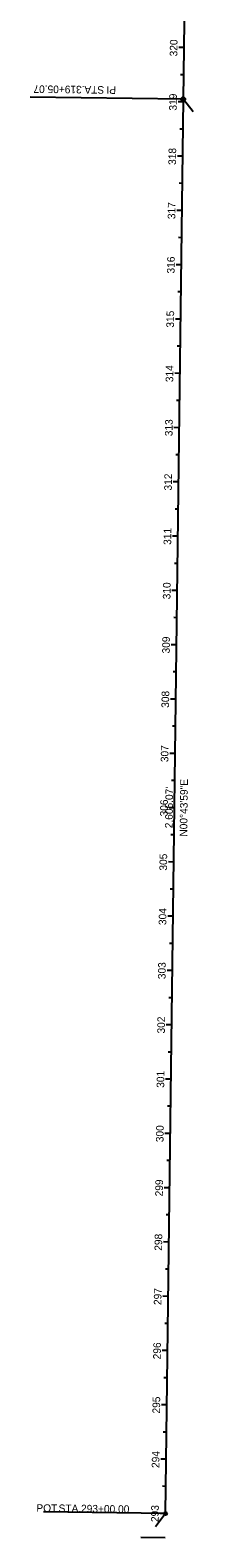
# Model space of a CAD drawing. Extents: x 1652268 to 1652613, y 604222 to 609731.
# Drawn here: x 1652268 to 1652586, y 604222 to 606999 of the extents above; entities that cross this region are included whole.
import ezdxf

# ---------------------------------------------------------------- set-up
doc = ezdxf.new("R2010")
doc.units = 0
for name, color, linetype in [('DT_X_Contour_Major', 7, 'Continuous'), ('DT_X_Contour_Minor', 7, 'Continuous'), ('DT_X_Contour_Text', 7, 'Continuous'), ('DT_X_Terrain_Ground_Line', 7, 'Continuous'), ('DT_X_Triangles', 7, 'Continuous'), ('PV_X_Curb', 7, 'Continuous')]:
    doc.layers.add(name, color=color, linetype=linetype)

msp = doc.modelspace()

# ---------------------------------------------------------------- linework, layer by layer
at = {"layer": 'DT_X_Contour_Minor'}
for p, q in [((1652550.1, 606872.1), (1652268, 606875.6)), ((1652517.5, 604267.2), (1652292.6, 604270.1))]:
    msp.add_line(p, q, dxfattribs=at)
for centre, radius in [((1652550.1, 606872.1), 3.76), ((1652517.5, 604267.2), 3)]:
    msp.add_circle(centre, radius, dxfattribs=at)
at = {"layer": 'DT_X_Contour_Text'}
for p, q in [((1652552, 606967), (1652542, 606967.1)), ((1652551.4, 606917), (1652545.4, 606917.1)), ((1652550.8, 606867), (1652540.8, 606867.1)), ((1652550.2, 606817), (1652544.2, 606817.1)), ((1652549.5, 606767), (1652539.5, 606767.1)), ((1652548.9, 606717), (1652542.9, 606717.1)), ((1652548.2, 606667), (1652538.2, 606667.1)), ((1652547.6, 606617), (1652541.6, 606617.1)), ((1652547, 606567), (1652537, 606567.2)), ((1652546.3, 606517), (1652540.3, 606517.1)), ((1652545.7, 606467), (1652535.7, 606467.2)), ((1652545, 606417), (1652539, 606417.1)), ((1652544.4, 606367), (1652534.4, 606367.2)), ((1652543.8, 606317), (1652537.8, 606317.1)), ((1652543.1, 606267), (1652533.1, 606267.2)), ((1652542.5, 606217.1), (1652536.5, 606217.1)), ((1652541.8, 606167.1), (1652531.8, 606167.2)), ((1652541.2, 606117.1), (1652535.2, 606117.1)), ((1652540.6, 606067.1), (1652530.6, 606067.2)), ((1652539.9, 606017.1), (1652533.9, 606017.1)), ((1652539.3, 605967.1), (1652529.3, 605967.2)), ((1652538.6, 605917.1), (1652532.6, 605917.2)), ((1652538, 605867.1), (1652528, 605867.2)), ((1652537.4, 605817.1), (1652531.4, 605817.2)), ((1652536.7, 605767.1), (1652526.7, 605767.2)), ((1652536.1, 605717.1), (1652530.1, 605717.2)), ((1652535.4, 605667.1), (1652525.4, 605667.2)), ((1652534.8, 605617.1), (1652528.8, 605617.2)), ((1652534.2, 605567.1), (1652524.2, 605567.2)), ((1652533.5, 605517.1), (1652527.5, 605517.2)), ((1652532.9, 605467.1), (1652522.9, 605467.2)), ((1652532.2, 605417.1), (1652526.2, 605417.2)), ((1652531.6, 605367.1), (1652521.6, 605367.2)), ((1652531, 605317.1), (1652525, 605317.2)), ((1652530.3, 605267.1), (1652520.3, 605267.3)), ((1652529.7, 605217.1), (1652523.7, 605217.2)), ((1652529, 605167.1), (1652519, 605167.3)), ((1652528.4, 605117.1), (1652522.4, 605117.2)), ((1652527.8, 605067.1), (1652517.8, 605067.3)), ((1652527.1, 605017.2), (1652521.1, 605017.2)), ((1652526.5, 604967.2), (1652516.5, 604967.3)), ((1652525.8, 604917.2), (1652519.8, 604917.2)), ((1652525.2, 604867.2), (1652515.2, 604867.3)), ((1652524.6, 604817.2), (1652518.6, 604817.2)), ((1652523.9, 604767.2), (1652513.9, 604767.3)), ((1652523.3, 604717.2), (1652517.3, 604717.3)), ((1652522.6, 604667.2), (1652512.7, 604667.3)), ((1652522, 604617.2), (1652516, 604617.3)), ((1652521.4, 604567.2), (1652511.4, 604567.3)), ((1652520.7, 604517.2), (1652514.7, 604517.3)), ((1652520.1, 604467.2), (1652510.1, 604467.3)), ((1652519.5, 604417.2), (1652513.5, 604417.3)), ((1652518.8, 604367.2), (1652508.8, 604367.3)), ((1652518.2, 604317.2), (1652512.2, 604317.3)), ((1652517.5, 604267.2), (1652507.5, 604267.3))]:
    msp.add_line(p, q, dxfattribs=at)
at = {"layer": 'DT_X_Terrain_Ground_Line'}
for p, q in [((1652550.9, 606872.1), (1652586.4, 609713.4)), ((1652517.5, 604267.2), (1652550.9, 606872.1))]:
    msp.add_line(p, q, dxfattribs=at)
at = {"layer": 'PV_X_Curb'}
for p, q in [((1652550.9, 606872.1), (1652568.6, 606849.5)), ((1652517.5, 604267.2), (1652499.1, 604242.9)), ((1652517, 604222.4), (1652472, 604223))]:
    msp.add_line(p, q, dxfattribs=at)

# ---------------------------------------------------------------- texts
at = {"layer": 'DT_X_Contour_Major'}
msp.add_text("2,605.07'", height=14, rotation=89.267, dxfattribs=at).set_placement((1652530.6, 605529.2))
at = {"layer": 'DT_X_Contour_Minor'}
for s, rotation, p in [('319+05.07', 179.2843, (1652363.2, 606896.6)), (' STA. ', 179.2843, (1652409.8, 606896)), ('PI', 179.2843, (1652426.4, 606895.8)), ('POT', 359.267, (1652279.5, 604270.4)), (' STA. ', 359.267, (1652315.2, 604270)), ('293+00.00', 359.267, (1652361.8, 604269.4))]:
    msp.add_text(s, height=14, rotation=rotation, dxfattribs=at).set_placement(p)
at = {"layer": 'DT_X_Contour_Text'}
for s, rotation, p in [('320', 89.2843, (1652539.3, 606950.8)), ('319', 89.267, (1652538.1, 606851)), ('318', 89.267, (1652536.8, 606750.9)), ('317', 89.267, (1652535.5, 606651)), ('316', 89.267, (1652534.2, 606550.9)), ('315', 89.267, (1652533, 606451.2)), ('314', 89.267, (1652531.7, 606350.8)), ('313', 89.267, (1652530.4, 606251.2)), ('312', 89.267, (1652529.1, 606151.2)), ('311', 89.267, (1652527.9, 606051.1)), ('310', 89.267, (1652526.6, 605950.9)), ('309', 89.267, (1652525.3, 605851.1)), ('308', 89.267, (1652524, 605751)), ('307', 89.267, (1652522.7, 605651)), ('306', 89.267, (1652521.5, 605551)), ('305', 89.267, (1652520.2, 605451.2)), ('304', 89.267, (1652518.9, 605350.9)), ('303', 89.267, (1652517.6, 605251.3)), ('302', 89.267, (1652516.3, 605151.2)), ('301', 89.267, (1652515.1, 605051.2)), ('300', 89.267, (1652513.8, 604951)), ('299', 89.267, (1652512.5, 604851.2)), ('298', 89.267, (1652511.2, 604751.1)), ('297', 89.267, (1652509.9, 604651.1)), ('296', 89.267, (1652508.7, 604551.1)), ('295', 89.267, (1652507.4, 604451.3)), ('294', 89.267, (1652506.1, 604351)), ('293', 89.267, (1652504.8, 604251.4))]:
    msp.add_text(s, height=14, rotation=rotation, dxfattribs=at).set_placement(p)
at = {"layer": 'DT_X_Triangles'}
msp.add_text('N00°43\'59"E', height=14, rotation=89.267, dxfattribs=at).set_placement((1652557.5, 605513.8))

doc.saveas('drawing.dxf')
